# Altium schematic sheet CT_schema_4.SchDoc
size 573 x 363 mm
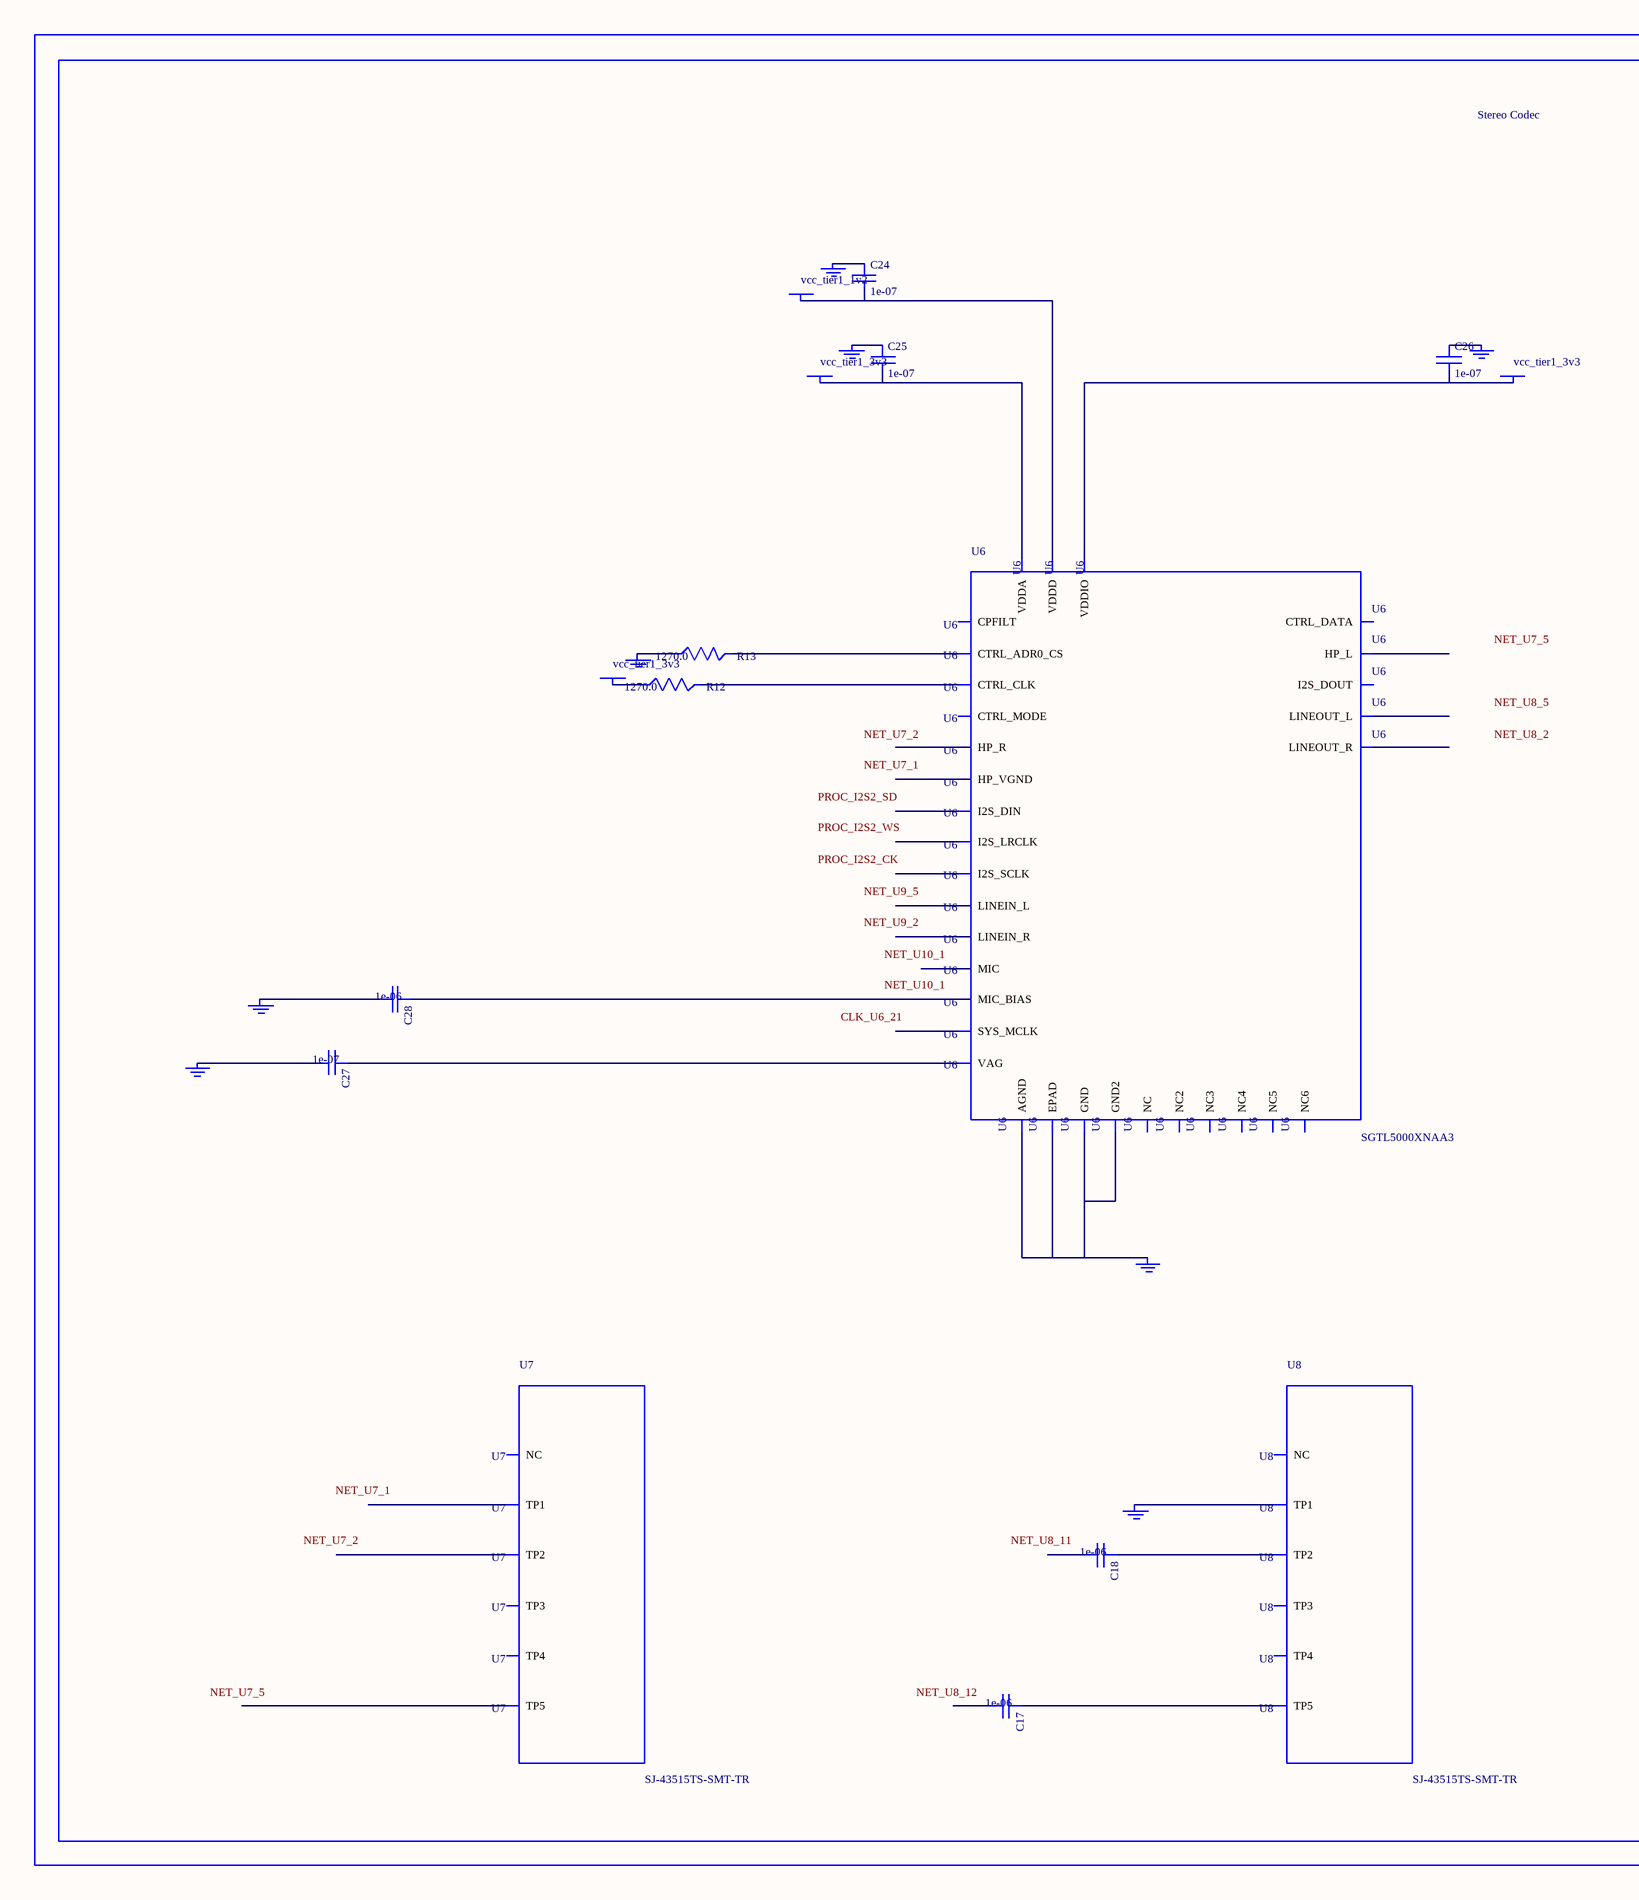
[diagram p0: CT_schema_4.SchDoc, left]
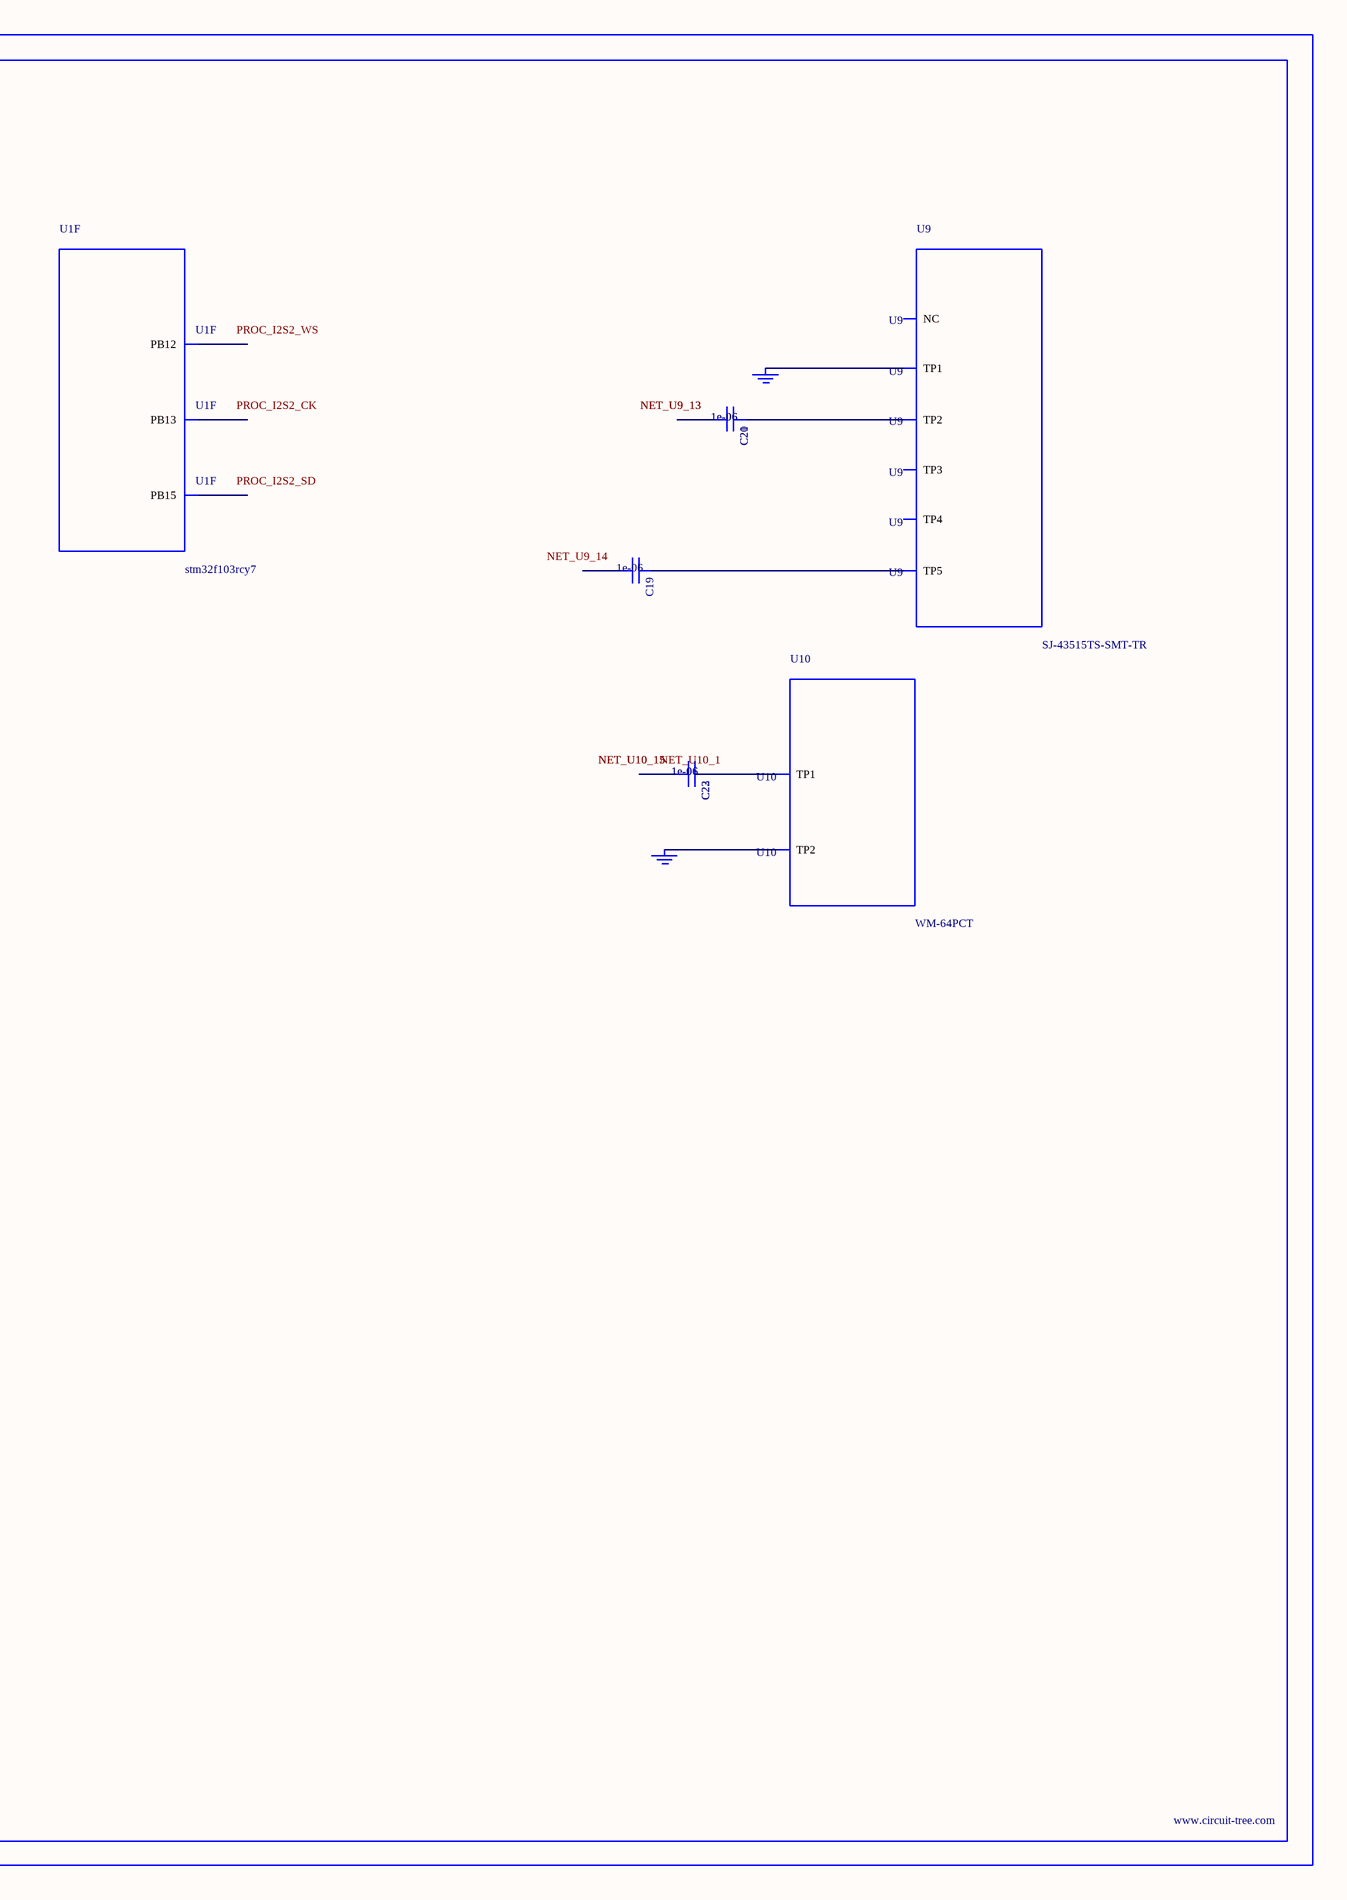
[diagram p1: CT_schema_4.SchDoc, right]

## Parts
BORDER3  (no value)
C17  1e-06  [C0603]
C18  1e-06  [C0603]
C19  1e-06  [C0603]
C20  1e-06  [C0603]
C21  1e-06  [C0603]
C22  1e-06  [C0603]
C23  1e-06  [C0603]
C24  1e-07  [C0402]
C25  1e-07  [C0402]
C26  1e-07  [C0402]
C27  1e-07  [C0402]
C28  1e-06  [C0603]
GND_INSTANCE_3_0  (no value)
GND_INSTANCE_3_1  (no value)
GND_INSTANCE_3_2  (no value)
GND_INSTANCE_3_3  (no value)
GND_INSTANCE_3_4  (no value)
GND_INSTANCE_3_5  (no value)
GND_INSTANCE_3_6  (no value)
GND_INSTANCE_3_7  (no value)
GND_INSTANCE_3_8  (no value)
GND_INSTANCE_3_9  (no value)
GND_INSTANCE_3_10  (no value)
POWER_INSTANCE_3_0  vcc_tier1_3v3
POWER_INSTANCE_3_1  vcc_tier1_3v3
POWER_INSTANCE_3_2  vcc_tier1_3v3
POWER_INSTANCE_3_3  vcc_tier1_1v2
R12  1270.0  [R0603]
R13  1270.0  [R0603]
U1  stm32f103rcy7  [WLCSP64]  (part F of 7)
U6  SGTL5000XNAA3  [QFN-32]
U7  SJ-43515TS-SMT-TR  [SJ-43515TS-SMT-TR]
U8  SJ-43515TS-SMT-TR  [SJ-43515TS-SMT-TR]
U9  SJ-43515TS-SMT-TR  [SJ-43515TS-SMT-TR]
U10  WM-64PCT  [WM-64PC]

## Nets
NetC17_1: C17.1 U8.5(TP5)
NetC18_1: C18.1 U8.2(TP2)
NetC19_1: C19.1 U9.5(TP5)
NetC20_1: C20.1 C21.1 U9.2(TP2)
NetC20_2: C20.2 C21.2
NetC22_1: C22.1 C23.1 U10.1(TP1)
NetC22_2: C22.2 C23.2
NetC24_1: C24.1 GND_INSTANCE_3_5.0(GND)
NetC24_2: C24.2 POWER_INSTANCE_3_3.0(PWR) U6.30(VDDD)
NetC25_1: C25.1 GND_INSTANCE_3_1.0(GND)
NetC25_2: C25.2 POWER_INSTANCE_3_0.0(PWR) U6.5(VDDA)
NetC26_1: C26.1 GND_INSTANCE_3_4.0(GND)
NetC26_2: C26.2 POWER_INSTANCE_3_1.0(PWR) U6.20(VDDIO)
NetC27_1: C27.1 U6.10(VAG)
NetC27_2: C27.2 GND_INSTANCE_3_2.0(GND)
NetC28_1: C28.1 U6.16(MIC_BIAS)
NetC28_2: C28.2 GND_INSTANCE_3_3.0(GND)
NetGND_INSTANCE_3_0_0: GND_INSTANCE_3_0.0(GND) U6.1(GND) U6.3(GND2) U6.7(AGND) U6.EXP(EPAD)
NetGND_INSTANCE_3_6_0: GND_INSTANCE_3_6.0(GND) R13.1
NetGND_INSTANCE_3_7_0: GND_INSTANCE_3_7.0(GND) U8.1(TP1)
NetGND_INSTANCE_3_8_0: GND_INSTANCE_3_8.0(GND) GND_INSTANCE_3_9.0(GND) U9.1(TP1)
NetGND_INSTANCE_3_10_0: GND_INSTANCE_3_10.0(GND) U10.2(TP2)
NetPOWER_INSTANCE_3_2_0: POWER_INSTANCE_3_2.0(PWR) R12.1
NetR12_2: R12.2 U6.29(CTRL_CLK)
NetR13_2: R13.2 U6.31(CTRL_ADR0_CS)

Not connected (* = marked no-connect by the designer): C17 2; C18 2; C19 2; U1 F1(PB15) G1(PB13) G2(PB12); U6 2(HP_R) 4(HP_VGND) 6(HP_L) 8(NC) 9(NC2) 11(LINEOUT_R) 12(LINEOUT_L) 13(LINEIN_R) 14(LINEIN_L) 15(MIC) 17(NC3) 18(CPFILT) 19(NC4) 21(SYS_MCLK) 22(NC5) 23(I2S_LRCLK) 24(I2S_SCLK) 25(I2S_DOUT) 26(I2S_DIN) 27(CTRL_DATA) 28(NC6) 32(CTRL_MODE); U7 1(TP1) 2(TP2) 3(TP3) 4(TP4) 5(TP5) 6(NC); U8 3(TP3) 4(TP4) 6(NC); U9 3(TP3) 4(TP4) 6(NC)

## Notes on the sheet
- Labels drawn without touching a wire or pin: CLK_U6_21, NET_U7_1, NET_U7_2, NET_U7_5, NET_U8_2, NET_U8_5, NET_U8_11, NET_U8_12, NET_U9_2, NET_U9_5, NET_U9_14, NET_U10_1, PROC_I2S2_CK, PROC_I2S2_SD, PROC_I2S2_WS

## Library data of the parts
BORDER3 = BORDER_PAGE3
C17-C23 C28 = C0603C105K3RACTU
C24-C27 = C0402C104K3RACTU
GND_INSTANCE_3_0-GND_INSTANCE_3_10 = GND
POWER_INSTANCE_3_0-POWER_INSTANCE_3_3 = PWR
R12 R13 = RC0603FR-071K27L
